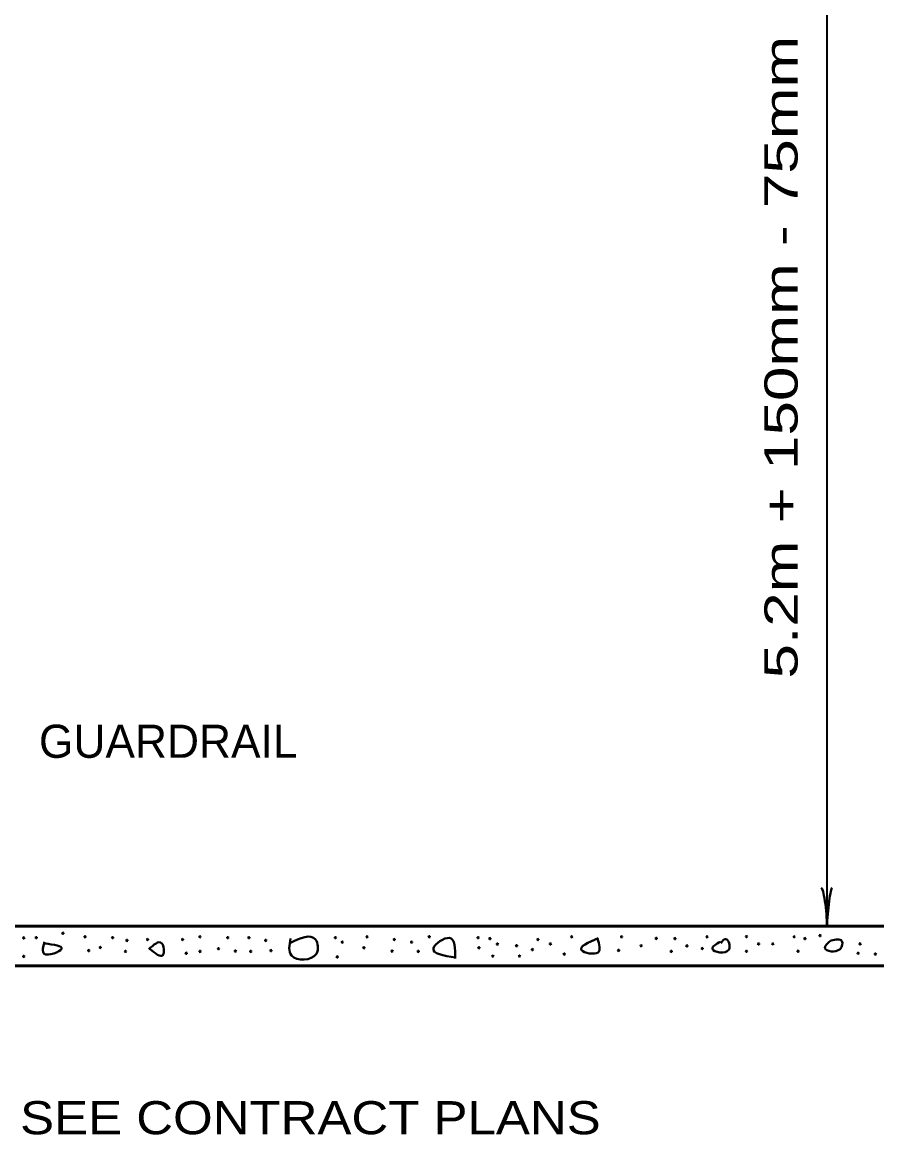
# Model space of a CAD drawing. Extents: x 14808 to 15663, y 10944 to 11488.
# Drawn here: x 14998.3 to 15075.7, y 11254.1 to 11354.9 of the extents above; entities that cross this region are included whole.
import ezdxf
from ezdxf.enums import TextEntityAlignment as Align

# ---------------------------------------------------------------- set-up
doc = ezdxf.new("R2010")
doc.units = 0
doc.header["$LTSCALE"] = 1.2
doc.layers.add('1', color=7, linetype='Continuous', lineweight=53)

msp = doc.modelspace()

# ---------------------------------------------------------------- linework, layer by layer
at = {"layer": '1', "lineweight": 35}
msp.add_line((15071.168, 11374.088), (15071.168, 11273.024), dxfattribs=at)
at = {"layer": '1'}
for points in [[(14994.385, 11273.024), (15144.385, 11273.024), (15144.385, 11276.623), (15179.229, 11276.623)], [(14994.385, 11273.001), (14994.385, 11269.424), (15147.085, 11269.424), (15147.085, 11276.623)]]:
    msp.add_lwpolyline(points, dxfattribs=at)
at = {"layer": '1', "lineweight": 40}
for centre in [(14998.471, 11271.947), (14999.605, 11271.975), (15002.015, 11272.375), (15004.02, 11272.058), (15006.52, 11271.975), (15014.416, 11272.053), (15016.935, 11271.975), (15018.851, 11271.975), (15026.683, 11271.975), (15029.555, 11272.053), (15035.181, 11272.058), (15039.597, 11271.975), (15048.077, 11272.053), (15052.587, 11272.053), (15055.726, 11271.908), (15060.318, 11272.053), (15063.891, 11272.075), (15068.209, 11272.053), (15070.556, 11272.158), (15005.397, 11271.086), (15007.813, 11271.731), (15009.686, 11271.808), (15012.852, 11271.808), (15016.101, 11270.975), (15020.375, 11271.731), (15027.301, 11271.57), (15029.266, 11271.059), (15032.015, 11271.808), (15033.582, 11271.57), (15039.68, 11271.059), (15040.669, 11271.892), (15041.347, 11271.392), (15043.084, 11271.247), (15044.513, 11270.892), (15045.013, 11271.808), (15046.144, 11271.409), (15054.358, 11271.247), (15057.419, 11271.892), (15058.502, 11271.225), (15059.892, 11270.992), (15064.988, 11271.409), (15066.277, 11271.409), (15069.176, 11271.892), (15074.169, 11271.409), (14998.471, 11270.281), (15004.354, 11270.809), (15007.686, 11270.725), (15013.185, 11270.559), (15014.435, 11270.725), (15017.637, 11270.764), (15019.017, 11270.725), (15020.851, 11270.809), (15026.849, 11270.225), (15031.81, 11270.764), (15034.181, 11270.725), (15040.93, 11270.309), (15043.346, 11270.309), (15047.394, 11270.492), (15052.31, 11270.825), (15057.085, 11270.725), (15063.891, 11270.742), (15068.557, 11270.742), (15073.999, 11270.559), (15075.556, 11270.492)]:
    msp.add_circle(centre, 0.06, dxfattribs=at)
for centre, major_axis, ratio, start_param, end_param in [((15070.837, 11274.333), (0.187, -2.143), 0.122415, 0.8963533, 3.1415927), ((15071.422, 11274.368), (0.211, 2.108), 0.07063, 6.2823074, 8.5597026)]:
    msp.add_ellipse(centre, major_axis=major_axis, ratio=ratio, start_param=start_param, end_param=end_param, dxfattribs=at)
for points in [[(15022.63, 11271.89), (15022.711, 11270.359), (15024.966, 11270.521), (15024.885, 11271.809), (15022.55, 11271.487)], [(15037.568, 11270.178), (15035.555, 11271.024), (15037.005, 11271.95), (15037.528, 11270.098)], [(15000.364, 11271.607), (15000.324, 11270.52), (15001.894, 11270.963), (15000.364, 11271.446)], [(15009.786, 11270.923), (15010.954, 11271.487), (15011.074, 11270.4), (15009.866, 11270.963)], [(15050.453, 11271.93), (15048.963, 11270.843), (15050.453, 11270.642), (15050.413, 11271.89)], [(15061.526, 11271.608), (15060.801, 11270.964), (15062.291, 11270.883), (15062.009, 11271.85), (15061.566, 11271.487)], [(15071.511, 11271.709), (15070.988, 11271.025), (15072.357, 11270.944), (15072.518, 11271.669), (15071.551, 11271.709)]]:
    msp.add_spline(points, degree=3, dxfattribs=at)

# ---------------------------------------------------------------- texts
at = {"layer": '1', "width": 1.4}
msp.add_text('5.2m + 150mm - 75mm', height=3, rotation=90, dxfattribs=at).set_placement((15068.517, 11324.552), align=Align.CENTER)
at = {"layer": '1'}
msp.add_text('GUARDRAIL', height=3, dxfattribs=at).set_placement((14999.85, 11288.265))
at = {"layer": '1', "width": 1.15}
msp.add_text('SEE CONTRACT PLANS', height=3, dxfattribs=at).set_placement((15024.419, 11254.166), align=Align.CENTER)

doc.saveas('drawing.dxf')
